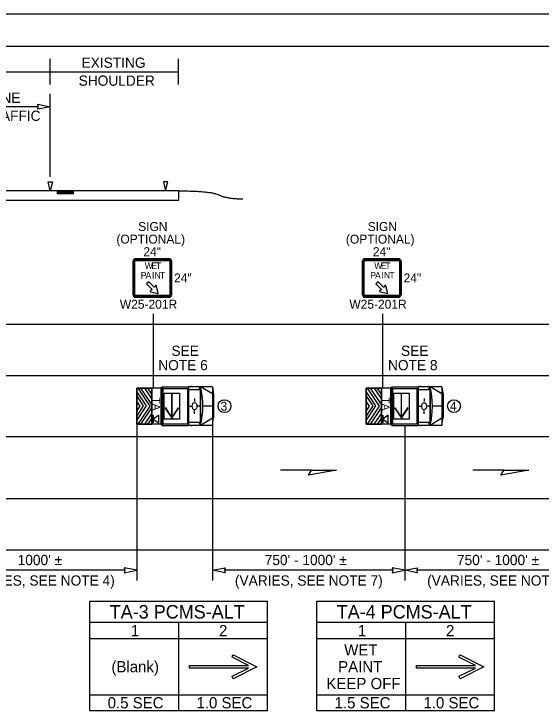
# Model space of a CAD drawing. Extents: x 0 to 17, y 0 to 11.
# Drawn here: x 8.57 to 12.68, y 5.55 to 11 of the extents above; entities that cross this region are included whole.
import ezdxf

# ---------------------------------------------------------------- set-up
doc = ezdxf.new("R2010")
doc.units = 0
for name, color, linetype in [('RD_ED_ShoulderPavedEdge', 7, 'Continuous'), ('RD_MK_LineEdgeWhite', 7, 'Continuous'), ('RD_MK_LineEdgeYellow', 7, 'Continuous'), ('RD_MK_LineLane', 7, 'Continuous'), ('SH_GI_PlotLimits', 7, 'Continuous'), ('SH_GI_SheetBorder3', 7, 'Continuous'), ('SH_TI_WZSectionCut', 7, 'Continuous'), ('TR_SN_ConstructionSigns', 7, 'Continuous'), ('TR_WZ_PortableChangeMessageSign', 7, 'Continuous'), ('TR_WZ_PortableSignMountBlk-Org', 7, 'Continuous'), ('TR_WZ_TransportableAttenuator', 7, 'Continuous'), ('TR_WZ_WorkZoneDetails', 7, 'Continuous'), ('TR_WZ_WorkZoneTextCurrent', 7, 'Continuous')]:
    doc.layers.add(name, color=color, linetype=linetype)

msp = doc.modelspace()

# ---------------------------------------------------------------- linework, layer by layer
at = {"layer": 'RD_ED_ShoulderPavedEdge'}
for p, q in [((1.8283, 8.5807), (16.62, 8.5807)), ((1.8283, 6.8207), (16.62, 6.8207))]:
    msp.add_line(p, q, dxfattribs=at)
at = {"layer": 'RD_MK_LineEdgeWhite'}
msp.add_line((1.8283, 7.2207), (16.62, 7.2207), dxfattribs=at)
at = {"layer": 'RD_MK_LineEdgeYellow'}
msp.add_line((1.8283, 8.1807), (16.62, 8.1807), dxfattribs=at)
at = {"layer": 'RD_MK_LineLane'}
msp.add_line((16.62, 7.7007), (1.8283, 7.7007), dxfattribs=at)
at = {"layer": 'SH_GI_PlotLimits'}
msp.add_lwpolyline([(0, 11), (17, 11), (17, 0), (0, 0)], close=True, dxfattribs=at)
at = {"layer": 'SH_GI_SheetBorder3'}
msp.add_line((1, 10.75), (16.75, 10.75), dxfattribs=at)
at = {"layer": 'SH_TI_WZSectionCut'}
for p, q in [((8.8546, 10.45), (8.8546, 10.65)), ((9.8546, 10.45), (9.8546, 10.65)), ((7.6546, 10.55), (8.8546, 10.55)), ((8.8546, 10.55), (9.8546, 10.55)), ((8.8546, 9.7297), (8.8546, 10.376)), ((8.7609, 10.276), (7.8484, 10.276)), ((9.8546, 9.6199), (5.4546, 9.6199)), ((9.0376, 9.6143), (8.9046, 9.6143)), ((9.0376, 9.6087), (8.9046, 9.6087)), ((9.0376, 9.603), (8.9046, 9.603)), ((9.0376, 9.5978), (8.9046, 9.5978)), ((9.8546, 9.6199), (9.8546, 9.5449)), ((9.8546, 9.5449), (5.4546, 9.5449))]:
    msp.add_line(p, q, dxfattribs=at)
for points in [[(8.8546, 10.276), (8.7564, 10.2567), (8.7609, 10.276), (8.7564, 10.2953)], [(8.838, 9.6897), (8.8713, 9.6897), (8.8547, 9.6199)]]:
    msp.add_lwpolyline(points, close=True, dxfattribs=at)
msp.add_lwpolyline([(9.7713, 9.6897), (9.7379, 9.6897), (9.7546, 9.6199), (9.7713, 9.6897)], dxfattribs=at)
msp.add_open_spline([(9.8546, 9.6199), (10.1058, 9.6201), (10.2313, 9.558), (10.3568, 9.5581)], degree=2, dxfattribs=at)
at = {"layer": 'TR_SN_ConstructionSigns'}
for p, q in [((9.5003, 9.0719), (9.5003, 8.8094)), ((9.5003, 8.8094), (9.5003, 9.0719)), ((9.5003, 9.0719), (9.5003, 8.8094)), ((9.505, 9.0719), (9.505, 8.8094)), ((9.5128, 8.8094), (9.5128, 9.0719)), ((9.7816, 9.0907), (9.5191, 9.0907)), ((9.5191, 9.0907), (9.7816, 9.0907)), ((9.7816, 9.0907), (9.5191, 9.0907)), ((9.7816, 9.086), (9.5191, 9.086)), ((9.5191, 9.0782), (9.7816, 9.0782)), ((9.7878, 9.0719), (9.7878, 8.8094)), ((9.7956, 8.8094), (9.7956, 9.0719)), ((9.8003, 8.8094), (9.8003, 9.0719)), ((9.8003, 9.0719), (9.8003, 8.8094)), ((9.8003, 8.8094), (9.8003, 9.0719)), ((11.2911, 9.072), (11.2911, 8.8095)), ((11.2911, 8.8095), (11.2911, 9.072)), ((11.2911, 9.072), (11.2911, 8.8095)), ((11.2958, 9.072), (11.2958, 8.8095)), ((11.3036, 8.8095), (11.3036, 9.072)), ((11.5723, 9.0907), (11.3098, 9.0907)), ((11.3098, 9.0907), (11.5723, 9.0907)), ((11.5723, 9.0907), (11.3098, 9.0907)), ((11.5723, 9.086), (11.3098, 9.086)), ((11.3098, 9.0782), (11.5723, 9.0782)), ((11.5786, 9.072), (11.5786, 8.8095)), ((11.5864, 8.8095), (11.5864, 9.072)), ((11.5911, 8.8095), (11.5911, 9.072)), ((11.5911, 9.072), (11.5911, 8.8095)), ((11.5911, 8.8095), (11.5911, 9.072)), ((9.6221, 8.9115), (9.6045, 8.8939)), ((9.6045, 8.8939), (9.6486, 8.8497)), ((9.6663, 8.8674), (9.6221, 8.9115)), ((11.4129, 8.9116), (11.3952, 8.8939)), ((11.3952, 8.8939), (11.4394, 8.8497)), ((11.4571, 8.8674), (11.4129, 8.9116)), ((9.6486, 8.8497), (9.6352, 8.8415)), ((9.6745, 8.8808), (9.6663, 8.8674)), ((9.6962, 8.8198), (9.683, 8.8796)), ((11.4394, 8.8497), (11.426, 8.8416)), ((11.4653, 8.8809), (11.4571, 8.8674)), ((11.4869, 8.8199), (11.4738, 8.8796)), ((9.7816, 8.8032), (9.5191, 8.8032)), ((9.5191, 8.7954), (9.7816, 8.7954)), ((9.5191, 8.7907), (9.7816, 8.7907)), ((9.7816, 8.7907), (9.5191, 8.7907)), ((9.5191, 8.7907), (9.7816, 8.7907)), ((9.6364, 8.833), (9.6962, 8.8198)), ((11.5723, 8.8032), (11.3098, 8.8032)), ((11.3098, 8.7954), (11.5723, 8.7954)), ((11.3098, 8.7907), (11.5723, 8.7907)), ((11.5723, 8.7907), (11.3098, 8.7907)), ((11.3098, 8.7907), (11.5723, 8.7907)), ((11.4272, 8.833), (11.4869, 8.8199))]:
    msp.add_line(p, q, dxfattribs=at)
for centre, radius, start, end in [((9.5191, 9.0719), 0.0188, 90, 180), ((9.5191, 9.0719), 0.0188, 90, 180), ((9.5191, 9.0719), 0.0188, 90, 180), ((9.5191, 9.0719), 0.0141, 90, 180), ((9.5191, 9.0719), 0.00625, 90, 180), ((9.7816, 9.0719), 0.0188, 0, 90), ((9.7816, 9.0719), 0.0188, 0, 90), ((9.7816, 9.0719), 0.0188, 0, 90), ((9.7816, 9.0719), 0.0141, 0, 90), ((9.7816, 9.0719), 0.00625, 0, 90), ((11.3098, 9.072), 0.0188, 90, 180), ((11.3098, 9.072), 0.0188, 90, 180), ((11.3098, 9.072), 0.0188, 90, 180), ((11.3098, 9.072), 0.0141, 90, 180), ((11.3098, 9.072), 0.00625, 90, 180), ((11.5723, 9.072), 0.0188, 0, 90), ((11.5723, 9.072), 0.0188, 0, 90), ((11.5723, 9.072), 0.0188, 0, 90), ((11.5723, 9.072), 0.0141, 0, 90), ((11.5723, 9.072), 0.00625, 0, 90), ((9.6376, 8.8375), 0.00469, 121.1441, 255.4258), ((9.6785, 8.8784), 0.00469, 14.5742, 148.8559), ((11.4284, 8.8376), 0.00469, 121.1441, 255.4258), ((11.4693, 8.8784), 0.00469, 14.5742, 148.8559), ((9.5191, 8.8094), 0.0188, 180, 270), ((9.5191, 8.8094), 0.0188, 180, 270), ((9.5191, 8.8094), 0.0188, 180, 270), ((9.5191, 8.8094), 0.0141, 180, 270), ((9.5191, 8.8094), 0.00625, 180, 270), ((9.7816, 8.8094), 0.0141, 270, 0), ((9.7816, 8.8094), 0.00625, 270, 0), ((9.7816, 8.8094), 0.0188, 270, 0), ((9.7816, 8.8094), 0.0188, 270, 0), ((9.7816, 8.8094), 0.0188, 270, 0), ((11.3098, 8.8095), 0.0188, 180, 270), ((11.3098, 8.8095), 0.0188, 180, 270), ((11.3098, 8.8095), 0.0188, 180, 270), ((11.3098, 8.8095), 0.0141, 180, 270), ((11.3098, 8.8095), 0.00625, 180, 270), ((11.5723, 8.8095), 0.0141, 270, 0), ((11.5723, 8.8095), 0.00625, 270, 0), ((11.5723, 8.8095), 0.0188, 270, 0), ((11.5723, 8.8095), 0.0188, 270, 0), ((11.5723, 8.8095), 0.0188, 270, 0)]:
    msp.add_arc(centre, radius, start, end, dxfattribs=at)
at = {"layer": 'TR_WZ_PortableChangeMessageSign'}
for p, q in [((9.1639, 6.4207), (10.5499, 6.4207)), ((9.1639, 5.5639), (9.1639, 6.4207)), ((10.5499, 5.5639), (10.5499, 6.4207)), ((10.9348, 6.4207), (12.3208, 6.4207)), ((10.9348, 5.5639), (10.9348, 6.4207)), ((12.3208, 5.5639), (12.3208, 6.4207)), ((10.5499, 6.2527), (9.1639, 6.2527)), ((9.8569, 5.5639), (9.8569, 6.2527)), ((12.3208, 6.2527), (10.9348, 6.2527)), ((11.6278, 5.5639), (11.6278, 6.2527)), ((9.8569, 6.1267), (9.1639, 6.1267)), ((10.5499, 6.1267), (9.8569, 6.1267)), ((11.6278, 6.1267), (10.9348, 6.1267)), ((12.3208, 6.1267), (11.6278, 6.1267)), ((10.2819, 6.0017), (10.4659, 5.9083)), ((12.0528, 6.0017), (12.2368, 5.9083)), ((9.9409, 5.8978), (9.9409, 5.9188)), ((9.9409, 5.9188), (10.4007, 5.9188)), ((10.4007, 5.8978), (9.9409, 5.8978)), ((11.7118, 5.8978), (11.7118, 5.9188)), ((11.7118, 5.9188), (12.1716, 5.9188)), ((12.1716, 5.8978), (11.7118, 5.8978)), ((9.1639, 5.6899), (9.8569, 5.6899)), ((9.8569, 5.6899), (10.5499, 5.6899)), ((10.9348, 5.6899), (11.6278, 5.6899)), ((11.6278, 5.6899), (12.3208, 5.6899)), ((10.5499, 5.5639), (9.1639, 5.5639)), ((12.3208, 5.5639), (10.9348, 5.5639))]:
    msp.add_line(p, q, dxfattribs=at)
for points in [[(10.4007, 5.9188), (10.2725, 5.9829), (10.2772, 5.9923), (10.2819, 6.0017)], [(12.1716, 5.9188), (12.0434, 5.9829), (12.0481, 5.9923), (12.0528, 6.0017)], [(10.4659, 5.9083), (10.2819, 5.8149), (10.2772, 5.8243), (10.2725, 5.8337), (10.4007, 5.8978)], [(12.2368, 5.9083), (12.0528, 5.8149), (12.0481, 5.8243), (12.0434, 5.8337), (12.1716, 5.8978)]]:
    msp.add_lwpolyline(points, dxfattribs=at)
at = {"layer": 'TR_WZ_PortableSignMountBlk-Org'}
for p, q in [((9.6581, 7.8696), (9.6581, 7.8096)), ((11.4489, 7.8696), (11.4489, 7.8096))]:
    msp.add_line(p, q, dxfattribs=at)
for points in [[(9.6581, 7.8396), (9.7012, 7.8096), (9.7012, 7.8696)], [(11.4489, 7.8396), (11.492, 7.8096), (11.492, 7.8696)]]:
    msp.add_lwpolyline(points, close=True, dxfattribs=at)
at = {"layer": 'TR_WZ_TransportableAttenuator'}
for p, q in [((9.5367, 8.082), (9.5622, 8.082)), ((9.5367, 8.082), (9.6303, 7.9411)), ((9.5622, 8.082), (9.5367, 8.082)), ((9.6469, 7.9536), (9.5622, 8.082)), ((9.5899, 8.082), (9.6153, 8.082)), ((9.6153, 8.082), (9.5899, 8.082)), ((9.5899, 8.082), (9.6469, 7.9951)), ((9.6469, 8.0343), (9.6153, 8.082)), ((9.7274, 8.082), (9.6469, 8.082)), ((9.6469, 7.8004), (9.6469, 8.082)), ((9.7179, 8.0768), (9.7179, 7.8049)), ((9.7223, 8.0859), (9.7267, 8.0859)), ((9.7267, 8.0859), (9.7267, 7.7958)), ((9.7274, 8.0908), (9.9305, 8.0908)), ((9.7274, 8.0908), (9.7274, 7.7908)), ((9.7274, 8.0815), (9.7274, 7.8004)), ((9.7331, 8.0789), (9.7331, 7.8028)), ((9.7331, 8.0789), (9.9248, 8.0789)), ((9.9248, 8.0789), (9.9248, 7.8028)), ((9.9305, 8.0908), (9.9305, 7.7908)), ((9.9333, 8.0908), (9.9333, 7.7908)), ((10.1198, 8.0908), (9.9333, 8.0908)), ((9.9587, 8.0951), (9.9475, 8.0951)), ((10.0248, 8.0908), (10.013, 8.0676)), ((10.0248, 8.0908), (10.0248, 7.7908)), ((10.0265, 8.0908), (10.0265, 7.7908)), ((10.1198, 8.0359), (10.0265, 8.0908)), ((10.1198, 8.0908), (10.1198, 7.7908)), ((10.1198, 8.0908), (10.1289, 8.0303)), ((11.3275, 8.082), (11.353, 8.082)), ((11.3275, 8.082), (11.421, 7.9411)), ((11.353, 8.082), (11.3275, 8.082)), ((11.4377, 7.9536), (11.353, 8.082)), ((11.3807, 8.082), (11.4061, 8.082)), ((11.4061, 8.082), (11.3807, 8.082)), ((11.3807, 8.082), (11.4377, 7.9951)), ((11.4377, 8.0343), (11.4061, 8.082)), ((11.5182, 8.082), (11.4377, 8.082)), ((11.4377, 7.8004), (11.4377, 8.082)), ((11.5086, 8.0768), (11.5086, 7.8049)), ((11.5131, 8.0859), (11.5175, 8.0859)), ((11.5175, 8.0859), (11.5175, 7.7958)), ((11.5182, 8.0908), (11.7213, 8.0908)), ((11.5182, 8.0908), (11.5182, 7.7908)), ((11.5182, 8.0815), (11.5182, 7.8004)), ((11.5239, 8.0789), (11.5239, 7.8028)), ((11.5239, 8.0789), (11.7155, 8.0789)), ((11.7155, 8.0789), (11.7155, 7.8028)), ((11.7213, 8.0908), (11.7213, 7.7908)), ((11.724, 8.0908), (11.724, 7.7908)), ((11.9106, 8.0908), (11.724, 8.0908)), ((11.7495, 8.0951), (11.7383, 8.0951)), ((11.8156, 8.0908), (11.8037, 8.0676)), ((11.8156, 8.0908), (11.8156, 7.7908)), ((11.8173, 8.0908), (11.8173, 7.7908)), ((11.9106, 8.0359), (11.8173, 8.0908)), ((11.9106, 8.0908), (11.9106, 7.7908)), ((11.9106, 8.0908), (11.9197, 8.0303)), ((9.5289, 8.0187), (9.5289, 8.0552)), ((9.6041, 7.942), (9.5289, 8.0552)), ((9.5289, 8.0552), (9.5289, 8.0187)), ((9.5289, 8.0187), (9.58, 7.9424)), ((9.6469, 8.0343), (9.6469, 7.9951)), ((9.6469, 7.9951), (9.6469, 8.0343)), ((10.0248, 8.0676), (9.9333, 8.0676)), ((10.1289, 8.0303), (10.1289, 7.8514)), ((11.3197, 8.0187), (11.3197, 8.0552)), ((11.3949, 7.942), (11.3197, 8.0552)), ((11.3197, 8.0552), (11.3197, 8.0187)), ((11.3197, 8.0187), (11.3707, 7.9424)), ((11.4377, 8.0343), (11.4377, 7.9951)), ((11.4377, 7.9951), (11.4377, 8.0343)), ((11.8156, 8.0676), (11.724, 8.0676)), ((11.9197, 8.0303), (11.9197, 7.8514)), ((9.5289, 7.9021), (9.5289, 7.9801)), ((9.555, 7.9413), (9.5289, 7.9801)), ((9.5289, 7.9801), (9.5289, 7.9021)), ((9.7179, 7.962), (9.7267, 7.9564)), ((9.9801, 8.0003), (9.98, 7.9761)), ((11.3197, 7.9021), (11.3197, 7.9801)), ((11.3458, 7.9413), (11.3197, 7.9801)), ((11.3197, 7.9801), (11.3197, 7.9021)), ((11.5086, 7.962), (11.5175, 7.9564)), ((11.7709, 8.0003), (11.7708, 7.9761)), ((9.58, 7.9424), (9.5289, 7.8656)), ((9.5289, 7.8288), (9.6041, 7.942)), ((9.5289, 7.9021), (9.555, 7.9413)), ((9.6303, 7.9411), (9.5366, 7.8001)), ((9.5617, 7.8001), (9.6469, 7.9285)), ((9.6469, 7.9536), (9.6469, 7.9285)), ((9.6469, 7.9285), (9.6469, 7.9536)), ((9.7179, 7.9197), (9.7267, 7.9254)), ((9.7202, 7.9409), (9.7243, 7.9409)), ((9.7223, 7.9451), (9.7223, 7.9366)), ((9.9404, 7.9411), (9.957, 7.941)), ((9.9615, 7.9403), (9.9615, 7.9403)), ((10.0197, 7.9411), (10.0031, 7.941)), ((10.1198, 7.9409), (10.0448, 7.9409)), ((11.3707, 7.9424), (11.3197, 7.8656)), ((11.3197, 7.8288), (11.3949, 7.942)), ((11.3197, 7.9021), (11.3458, 7.9413)), ((11.421, 7.9411), (11.3274, 7.8001)), ((11.3525, 7.8001), (11.4377, 7.9285)), ((11.4377, 7.9536), (11.4377, 7.9285)), ((11.4377, 7.9285), (11.4377, 7.9536)), ((11.5086, 7.9197), (11.5175, 7.9254)), ((11.511, 7.9409), (11.5151, 7.9409)), ((11.5131, 7.9451), (11.5131, 7.9366)), ((11.7311, 7.9411), (11.7477, 7.941)), ((11.7523, 7.9403), (11.7523, 7.9403)), ((11.8105, 7.9411), (11.7939, 7.941)), ((11.9106, 7.9409), (11.8356, 7.9409)), ((9.5289, 7.8288), (9.5289, 7.8656)), ((9.5289, 7.8656), (9.5289, 7.8288)), ((9.6469, 7.887), (9.5892, 7.8001)), ((9.6469, 7.887), (9.6469, 7.8455)), ((9.6469, 7.8455), (9.6469, 7.887)), ((9.9801, 7.8814), (9.98, 7.9057)), ((11.3197, 7.8288), (11.3197, 7.8656)), ((11.3197, 7.8656), (11.3197, 7.8288)), ((11.4377, 7.887), (11.38, 7.8001)), ((11.4377, 7.887), (11.4377, 7.8455)), ((11.4377, 7.8455), (11.4377, 7.887)), ((11.7709, 7.8814), (11.7708, 7.9057)), ((9.5617, 7.8001), (9.5366, 7.8001)), ((9.5366, 7.8001), (9.5617, 7.8001)), ((9.6162, 7.8001), (9.5892, 7.8001)), ((9.5892, 7.8001), (9.6162, 7.8001)), ((9.6162, 7.8001), (9.6469, 7.8455)), ((9.7274, 7.8004), (9.6469, 7.8004)), ((9.7331, 7.8028), (9.9248, 7.8028)), ((10.0248, 7.8141), (9.9333, 7.8141)), ((10.015, 7.8141), (10.0248, 7.7908)), ((10.1198, 7.8458), (10.0265, 7.7908)), ((10.1198, 7.7908), (10.1289, 7.8514)), ((11.3525, 7.8001), (11.3274, 7.8001)), ((11.3274, 7.8001), (11.3525, 7.8001)), ((11.407, 7.8001), (11.38, 7.8001)), ((11.38, 7.8001), (11.407, 7.8001)), ((11.407, 7.8001), (11.4377, 7.8455)), ((11.5182, 7.8004), (11.4377, 7.8004)), ((11.5239, 7.8028), (11.7155, 7.8028)), ((11.8156, 7.8141), (11.724, 7.8141)), ((11.8058, 7.8141), (11.8156, 7.7908)), ((11.9106, 7.8458), (11.8173, 7.7908)), ((11.9106, 7.7908), (11.9197, 7.8514)), ((9.7223, 7.7958), (9.7267, 7.7958)), ((9.7274, 7.7908), (9.9305, 7.7908)), ((10.1198, 7.7908), (9.9333, 7.7908)), ((9.9587, 7.7867), (9.9475, 7.7867)), ((11.5131, 7.7958), (11.5175, 7.7958)), ((11.5182, 7.7908), (11.7213, 7.7908)), ((11.9106, 7.7908), (11.724, 7.7908)), ((11.7495, 7.7867), (11.7383, 7.7867))]:
    msp.add_line(p, q, dxfattribs=at)
for points in [[(9.6469, 7.8001), (9.5289, 7.8001), (9.5289, 8.082), (9.6469, 8.082)], [(11.4377, 7.8001), (11.3197, 7.8001), (11.3197, 8.082), (11.4377, 8.082)], [(9.7431, 8.0427), (9.8631, 8.0427), (9.8631, 7.8391), (9.7431, 7.8391)], [(9.8011, 8.0345), (9.8011, 7.8575), (9.8051, 7.8575), (9.8051, 8.0345)], [(11.5339, 8.0427), (11.6539, 8.0427), (11.6539, 7.8391), (11.5339, 7.8391)], [(11.5919, 8.0345), (11.5919, 7.8575), (11.5959, 7.8575), (11.5959, 8.0345)], [(9.7515, 7.9248), (9.8031, 7.8473), (9.8011, 7.8575), (9.7548, 7.927)], [(9.8031, 7.8473), (9.8548, 7.9248), (9.8515, 7.927), (9.8051, 7.8575)], [(11.5423, 7.9248), (11.5939, 7.8473), (11.5919, 7.8575), (11.5456, 7.927)], [(11.5939, 7.8473), (11.6456, 7.9248), (11.6423, 7.927), (11.5959, 7.8575)], [(9.8031, 7.8473), (9.8051, 7.8575), (9.8011, 7.8575)], [(11.5939, 7.8473), (11.5959, 7.8575), (11.5919, 7.8575)]]:
    msp.add_lwpolyline(points, close=True, dxfattribs=at)
for points in [[(9.6469, 8.082), (9.5289, 8.082), (9.5289, 7.8001), (9.6469, 7.8004)], [(11.4377, 8.082), (11.3197, 8.082), (11.3197, 7.8001), (11.4377, 7.8004)]]:
    msp.add_lwpolyline(points, dxfattribs=at)
for centre, major_axis, start_param, end_param in [((9.7223, 8.0768), (0, 0.00916), 6.283185, 7.853982), ((9.8932, 7.9408), (0, 0.3148), 4.215852, 5.209111), ((11.5131, 8.0768), (0, 0.00916), 6.283185, 7.853982), ((11.684, 7.9408), (0, 0.3148), 4.215852, 5.209111), ((9.7223, 7.8049), (0, -0.00916), 4.712389, 6.283185), ((11.5131, 7.8049), (0, -0.00916), 4.712389, 6.283185)]:
    msp.add_ellipse(centre, major_axis=major_axis, ratio=0.481608, start_param=start_param, end_param=end_param, dxfattribs=at)
for centre, major_axis, ratio in [((9.98, 7.9409), (0, -0.0289), 0.642144), ((9.98, 7.9409), (0, 0.0289), 0.642144), ((11.7708, 7.9409), (0, -0.0289), 0.642144), ((11.7708, 7.9409), (0, 0.0289), 0.642144), ((9.7223, 7.9409), (0, -0.00423), 0.481608), ((11.5131, 7.9409), (0, -0.00423), 0.481608)]:
    msp.add_ellipse(centre, major_axis=major_axis, ratio=ratio, dxfattribs=at)
at = {"layer": 'TR_WZ_WorkZoneDetails'}
for p, q in [((9.6568, 8.6607), (9.6568, 8.082)), ((11.4476, 8.6607), (11.4476, 8.082)), ((9.529, 7.8001), (9.529, 6.5807)), ((10.1196, 7.7908), (10.1196, 6.5807)), ((11.6197, 7.7908), (11.6197, 6.5807)), ((10.892, 7.4414), (10.6509, 7.4414)), ((12.392, 7.4414), (12.1509, 7.4414)), ((9.4353, 6.6607), (8.1227, 6.6607)), ((11.526, 6.6607), (10.2133, 6.6607)), ((13.0259, 6.6607), (11.7135, 6.6607))]:
    msp.add_line(p, q, dxfattribs=at)
for points in [[(11.0885, 7.4414), (10.8697, 7.4029), (10.892, 7.4414)], [(12.5885, 7.4414), (12.3697, 7.4029), (12.392, 7.4414)], [(9.529, 6.6607), (9.4307, 6.68), (9.4353, 6.6607), (9.4307, 6.6415)], [(10.1196, 6.6607), (10.2179, 6.68), (10.2133, 6.6607), (10.2179, 6.6415)], [(11.6197, 6.6607), (11.5215, 6.68), (11.526, 6.6607), (11.5215, 6.6415)], [(11.6197, 6.6607), (11.718, 6.68), (11.7135, 6.6607), (11.718, 6.6415)]]:
    msp.add_lwpolyline(points, close=True, dxfattribs=at)
for centre in [(10.2135, 7.9407), (12.0044, 7.9407)]:
    msp.add_circle(centre, 0.05, dxfattribs=at)

# ---------------------------------------------------------------- texts
at = {"layer": 'SH_TI_WZSectionCut'}
for s, p in [('EXISTING', (9.0986, 10.58)), ('SHOULDER', (9.0757, 10.44))]:
    msp.add_text(s, height=0.08, rotation=360, dxfattribs=at).set_placement(p)
for s, p in [("10' MIN LANE", (7.9472, 10.306)), ('OPEN TO TRAFFIC', (7.8155, 10.166))]:
    msp.add_text(s, height=0.08, dxfattribs=at).set_placement(p)
at = {"layer": 'TR_SN_ConstructionSigns'}
for s, height, p in [('SIGN', 0.07, (9.54, 9.3067)), ('SIGN', 0.07, (11.3307, 9.3067)), ('(OPTIONAL)', 0.07, (9.3702, 9.2087)), ('(OPTIONAL)', 0.07, (11.161, 9.2087)), ('24"', 0.07, (9.5808, 9.1107)), ('24"', 0.07, (11.3716, 9.1107)), ('W', 0.05, (9.5913, 9.0115)), ('E', 0.05, (9.6433, 9.0115)), ('T', 0.05, (9.6783, 9.0115)), ('W', 0.05, (11.3821, 9.0116)), ('E', 0.05, (11.4341, 9.0116)), ('T', 0.05, (11.4691, 9.0116)), ('P', 0.05, (9.5606, 8.9365)), ('A', 0.05, (9.5976, 8.9365)), ('I', 0.05, (9.6476, 8.9365)), ('N', 0.05, (9.6676, 8.9365)), ('T', 0.05, (9.7091, 8.9365)), ('24"', 0.07, (9.8203, 8.9057)), ('P', 0.05, (11.3513, 8.9366)), ('A', 0.05, (11.3883, 8.9366)), ('I', 0.05, (11.4383, 8.9366)), ('N', 0.05, (11.4583, 8.9366)), ('T', 0.05, (11.4998, 8.9366)), ('24"', 0.07, (11.6111, 8.9057)), ('W25-201R', 0.07, (9.3971, 8.7007)), ('W25-201R', 0.07, (11.1879, 8.7007))]:
    msp.add_text(s, height=height, dxfattribs=at).set_placement(p)
at = {"layer": 'TR_WZ_PortableChangeMessageSign'}
for s, height, p in [('TA-3 PCMS-ALT', 0.105, (9.3181, 6.2842)), ('TA-4 PCMS-ALT', 0.105, (11.0891, 6.2842)), ('1', 0.0875, (9.483, 6.146)), ('2', 0.0875, (10.1709, 6.146)), ('1', 0.0875, (11.2539, 6.146)), ('2', 0.0875, (11.9419, 6.146)), ('WET', 0.0875, (11.1476, 5.9958)), ('(Blank)', 0.0875, (9.3316, 5.8646)), ('PAINT', 0.0875, (11.1005, 5.8646)), ('KEEP OFF', 0.0875, (11.0087, 5.7333)), ('0.5 SEC', 0.0875, (9.3022, 5.5832)), ('1.0 SEC', 0.0875, (9.9952, 5.5832)), ('1.5 SEC', 0.0875, (11.0731, 5.5832)), ('1.0 SEC', 0.0875, (11.7661, 5.5832))]:
    msp.add_text(s, height=height, rotation=360, dxfattribs=at).set_placement(p)
at = {"layer": 'TR_WZ_TransportableAttenuator'}
for p in [(9.6517, 8.0092), (11.4425, 8.0092)]:
    msp.add_text('TA', height=0.06, rotation=270, dxfattribs=at).set_placement(p)
at = {"layer": 'TR_WZ_WorkZoneDetails'}
for s, p in [('3', (10.1829, 7.9057)), ('4', (11.973, 7.9057))]:
    msp.add_text(s, height=0.07, dxfattribs=at).set_placement(p)
at = {"layer": 'TR_WZ_WorkZoneTextCurrent'}
for s, p in [('SEE', (9.7996, 8.3327)), ('SEE', (11.5911, 8.3327)), ('NOTE 6', (9.6968, 8.2207)), ('NOTE 8', (11.4895, 8.2207)), ("1000' ±", (8.5999, 6.7007)), ("750' - 1000' ±", (10.5275, 6.7007)), ("750' - 1000' ±", (12.0275, 6.7007)), ('(VARIES, SEE NOTE 4)', (8.2044, 6.5407)), ('(VARIES, SEE NOTE 7)', (10.295, 6.5407)), ('(VARIES, SEE NOTE 7)', (11.795, 6.5407))]:
    msp.add_text(s, height=0.08, dxfattribs=at).set_placement(p)

doc.saveas('drawing.dxf')
